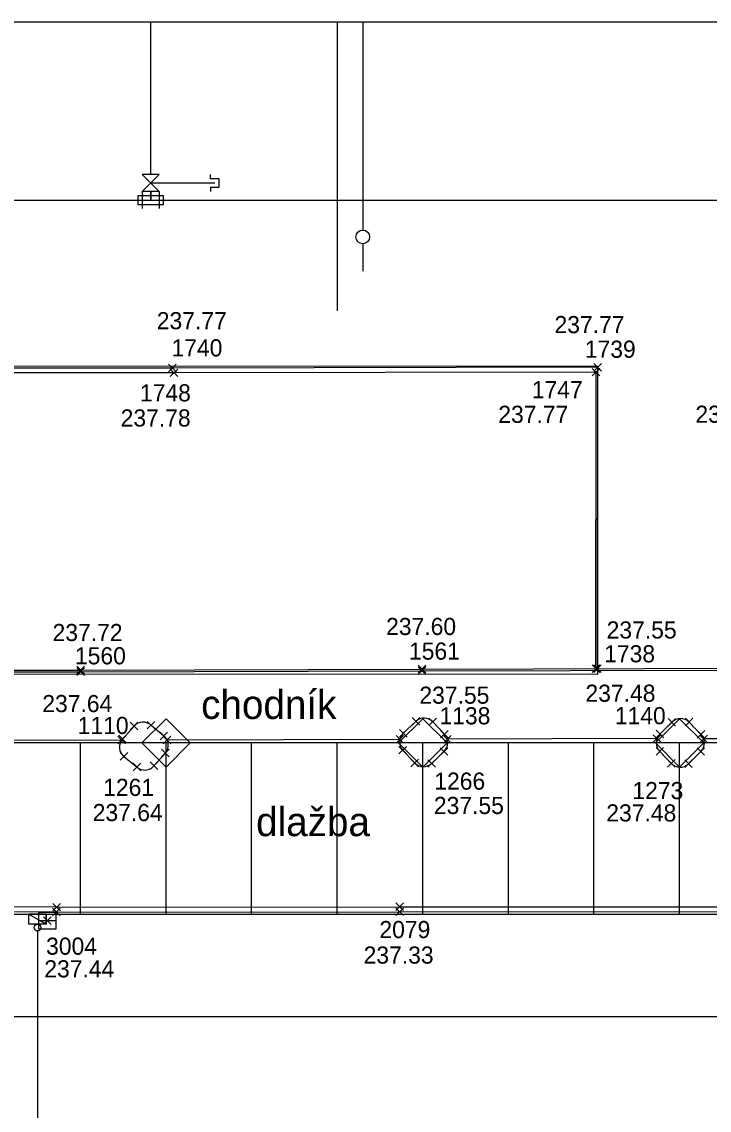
# Model space of a CAD drawing. Extents: x -264165 to -263733, y -1242319 to -1242245.
# Drawn here: x -263871.28 to -263851.2, y -1242276.71 to -1242244.94 of the extents above; entities that cross this region are included whole.
import ezdxf

# ---------------------------------------------------------------- set-up
doc = ezdxf.new("R2010")
doc.units = 0
for name, color, linetype in [('KFA_BOD_CISLO', 7, 'Continuous'), ('KFA_BOD_SYMBOL', 7, 'Continuous'), ('KFA_BOD_VYSKA', 7, 'Continuous'), ('KFA_SO_20-2_OBRUBNIKY_DOLNA_HRANA', 7, 'Continuous'), ('KFA_SO_20-2_OBRUBNIKY_HORNA_HRANA', 7, 'Continuous'), ('KFA_UV_BOD_CISLO', 7, 'Continuous'), ('KFA_UV_BOD_SYMBOL', 7, 'Continuous'), ('KFA_UV_BOD_VYSKA', 7, 'Continuous'), ('POPIS', 7, 'Continuous'), ('PROJEKT_OBRUBNIKY_KOMUNIKACIE', 7, 'Continuous'), ('PROJEKT_TDZ_VODOROVNE', 7, 'Continuous'), ('RAM_NA_TLAC_1-250', 7, 'Continuous'), ('SITUACIA_DSP_2D', 7, 'Continuous'), ('ULICNA_VPUST_POKLOP', 7, 'Continuous')]:
    doc.layers.add(name, color=color, linetype=linetype)

msp = doc.modelspace()

# ---------------------------------------------------------------- linework, layer by layer
at = {"layer": 'KFA_BOD_SYMBOL'}
for p, q in [((-263866.993, -1242255.153), (-263866.772, -1242254.931)), ((-263866.772, -1242255.153), (-263866.993, -1242254.931)), ((-263866.946, -1242255.292), (-263866.725, -1242255.072)), ((-263866.725, -1242255.292), (-263866.946, -1242255.072)), ((-263854.617, -1242255.272), (-263854.396, -1242255.052)), ((-263854.396, -1242255.272), (-263854.617, -1242255.052)), ((-263854.568, -1242255.13), (-263854.347, -1242254.91)), ((-263854.347, -1242255.13), (-263854.568, -1242254.91)), ((-263869.674, -1242263.968), (-263869.453, -1242263.747)), ((-263869.453, -1242263.968), (-263869.674, -1242263.747)), ((-263869.674, -1242264.018), (-263869.453, -1242263.796)), ((-263869.453, -1242264.018), (-263869.674, -1242263.796)), ((-263859.704, -1242263.938), (-263859.482, -1242263.717)), ((-263859.482, -1242263.938), (-263859.704, -1242263.717)), ((-263859.704, -1242263.988), (-263859.482, -1242263.766)), ((-263859.482, -1242263.988), (-263859.704, -1242263.766)), ((-263854.622, -1242263.926), (-263854.4, -1242263.704)), ((-263854.4, -1242263.926), (-263854.622, -1242263.704)), ((-263854.576, -1242263.926), (-263854.355, -1242263.704)), ((-263854.355, -1242263.926), (-263854.576, -1242263.704)), ((-263868.116, -1242265.603), (-263867.894, -1242265.383)), ((-263867.894, -1242265.603), (-263868.116, -1242265.383)), ((-263867.616, -1242265.576), (-263867.394, -1242265.355)), ((-263867.394, -1242265.576), (-263867.616, -1242265.355)), ((-263859.882, -1242265.467), (-263859.66, -1242265.245)), ((-263859.66, -1242265.467), (-263859.882, -1242265.245)), ((-263859.389, -1242265.48), (-263859.167, -1242265.258)), ((-263859.167, -1242265.48), (-263859.389, -1242265.258)), ((-263852.404, -1242265.492), (-263852.182, -1242265.271)), ((-263852.182, -1242265.492), (-263852.404, -1242265.271)), ((-263851.899, -1242265.487), (-263851.678, -1242265.265)), ((-263851.678, -1242265.487), (-263851.899, -1242265.265)), ((-263868.478, -1242266.014), (-263868.257, -1242265.792)), ((-263868.257, -1242266.014), (-263868.478, -1242265.792)), ((-263868.451, -1242265.981), (-263868.23, -1242265.761)), ((-263868.23, -1242265.981), (-263868.451, -1242265.761)), ((-263867.245, -1242265.891), (-263867.024, -1242265.671)), ((-263867.024, -1242265.891), (-263867.245, -1242265.671)), ((-263867.149, -1242266.012), (-263866.927, -1242265.791)), ((-263866.927, -1242266.012), (-263867.149, -1242265.791)), ((-263860.349, -1242265.991), (-263860.128, -1242265.769)), ((-263860.128, -1242265.991), (-263860.349, -1242265.769)), ((-263860.252, -1242265.812), (-263860.03, -1242265.592)), ((-263860.03, -1242265.812), (-263860.252, -1242265.592)), ((-263859.047, -1242265.84), (-263858.826, -1242265.62)), ((-263858.826, -1242265.84), (-263859.047, -1242265.62)), ((-263858.964, -1242265.988), (-263858.742, -1242265.766)), ((-263858.742, -1242265.988), (-263858.964, -1242265.766)), ((-263852.835, -1242265.965), (-263852.614, -1242265.745)), ((-263852.614, -1242265.965), (-263852.835, -1242265.745)), ((-263852.747, -1242265.833), (-263852.525, -1242265.612)), ((-263852.525, -1242265.833), (-263852.747, -1242265.612)), ((-263851.555, -1242265.846), (-263851.334, -1242265.624)), ((-263851.334, -1242265.846), (-263851.555, -1242265.624)), ((-263851.475, -1242265.978), (-263851.253, -1242265.758)), ((-263851.253, -1242265.978), (-263851.475, -1242265.758)), ((-263867.197, -1242266.393), (-263866.976, -1242266.171)), ((-263866.976, -1242266.393), (-263867.197, -1242266.171)), ((-263860.269, -1242266.306), (-263860.047, -1242266.085)), ((-263860.047, -1242266.306), (-263860.269, -1242266.085)), ((-263859.058, -1242266.345), (-263858.837, -1242266.123)), ((-263858.837, -1242266.345), (-263859.058, -1242266.123)), ((-263852.756, -1242266.343), (-263852.535, -1242266.122)), ((-263852.535, -1242266.343), (-263852.756, -1242266.122)), ((-263851.558, -1242266.343), (-263851.337, -1242266.123)), ((-263851.337, -1242266.343), (-263851.558, -1242266.123)), ((-263868.41, -1242266.488), (-263868.189, -1242266.266)), ((-263868.189, -1242266.488), (-263868.41, -1242266.266)), ((-263859.916, -1242266.678), (-263859.694, -1242266.458)), ((-263859.694, -1242266.678), (-263859.916, -1242266.458)), ((-263859.421, -1242266.694), (-263859.2, -1242266.474)), ((-263859.2, -1242266.694), (-263859.421, -1242266.474)), ((-263852.42, -1242266.693), (-263852.198, -1242266.471)), ((-263852.198, -1242266.693), (-263852.42, -1242266.471)), ((-263851.919, -1242266.704), (-263851.698, -1242266.482)), ((-263851.698, -1242266.704), (-263851.919, -1242266.482)), ((-263868.028, -1242266.802), (-263867.807, -1242266.58)), ((-263867.807, -1242266.802), (-263868.028, -1242266.58)), ((-263867.531, -1242266.759), (-263867.31, -1242266.539)), ((-263867.31, -1242266.759), (-263867.531, -1242266.539)), ((-263870.381, -1242271.034), (-263870.16, -1242270.812)), ((-263870.16, -1242271.034), (-263870.381, -1242270.812)), ((-263870.378, -1242270.889), (-263870.157, -1242270.667)), ((-263870.157, -1242270.889), (-263870.378, -1242270.667)), ((-263860.357, -1242271.025), (-263860.136, -1242270.803)), ((-263860.136, -1242271.025), (-263860.357, -1242270.803)), ((-263860.355, -1242270.877), (-263860.133, -1242270.656)), ((-263860.133, -1242270.877), (-263860.355, -1242270.656))]:
    msp.add_line(p, q, dxfattribs=at)
at = {"layer": 'KFA_SO_20-2_OBRUBNIKY_DOLNA_HRANA'}
for points in [[(-263870.27, -1242270.923), (-263879.971, -1242270.913), (-263889.978, -1242270.919), (-263899.995, -1242270.919), (-263908.997, -1242270.923), (-263917.4, -1242270.885)], [(-263870.268, -1242270.778), (-263879.968, -1242270.77), (-263889.973, -1242270.776), (-263899.989, -1242270.776), (-263908.993, -1242270.778), (-263917.158, -1242270.747)], [(-263870.27, -1242270.923), (-263860.247, -1242270.914), (-263850.285, -1242270.903), (-263840.274, -1242270.913), (-263830.254, -1242270.929), (-263819.233, -1242270.965)], [(-263870.268, -1242270.778), (-263860.244, -1242270.766), (-263850.281, -1242270.766), (-263840.271, -1242270.772), (-263830.256, -1242270.782), (-263819.239, -1242270.817)]]:
    msp.add_lwpolyline(points, dxfattribs=at)
at = {"layer": 'KFA_SO_20-2_OBRUBNIKY_HORNA_HRANA'}
for p, q in [((-263868.34, -1242265.871), (-263868.005, -1242265.493)), ((-263867.505, -1242265.465), (-263867.134, -1242265.781)), ((-263860.141, -1242265.702), (-263859.771, -1242265.356)), ((-263859.278, -1242265.369), (-263858.937, -1242265.73)), ((-263852.636, -1242265.722), (-263852.293, -1242265.381)), ((-263851.789, -1242265.376), (-263851.444, -1242265.735)), ((-263852.725, -1242265.855), (-263858.853, -1242265.877)), ((-263845.254, -1242265.858), (-263851.364, -1242265.868)), ((-263868.367, -1242265.903), (-263874.969, -1242265.925)), ((-263860.238, -1242265.88), (-263867.038, -1242265.901)), ((-263868.3, -1242266.377), (-263867.917, -1242266.691)), ((-263867.086, -1242266.282), (-263867.421, -1242266.649)), ((-263859.805, -1242266.568), (-263860.158, -1242266.195)), ((-263858.948, -1242266.234), (-263859.311, -1242266.584)), ((-263852.309, -1242266.582), (-263852.645, -1242266.232)), ((-263851.448, -1242266.233), (-263851.808, -1242266.593))]:
    msp.add_line(p, q, dxfattribs=at)
for points in [[(-263854.465, -1242263.815), (-263854.458, -1242255.02), (-263866.883, -1242255.042), (-263883.752, -1242255.044), (-263902.029, -1242255.047), (-263909.175, -1242255.048), (-263919.956, -1242255.04), (-263920.002, -1242255.04)], [(-263854.511, -1242263.815), (-263854.507, -1242255.162), (-263866.835, -1242255.182), (-263883.768, -1242255.184), (-263902.097, -1242255.191), (-263916.995, -1242263.915)], [(-263909.527, -1242263.897), (-263899.537, -1242263.895), (-263889.544, -1242263.882), (-263879.556, -1242263.864), (-263869.563, -1242263.857), (-263859.593, -1242263.827), (-263846.594, -1242263.797), (-263839.607, -1242263.784)], [(-263909.527, -1242263.947), (-263899.537, -1242263.945), (-263889.544, -1242263.932), (-263879.556, -1242263.914), (-263869.563, -1242263.907), (-263859.593, -1242263.877), (-263846.594, -1242263.847), (-263839.607, -1242263.834)]]:
    msp.add_lwpolyline(points, dxfattribs=at)
for centre, major_axis, ratio, start_param, end_param in [((-263867.741, -1242265.732), (-0.28, -0.22), 0.999509, 3.322445, 4.88112), ((-263859.531, -1242265.608), (-0.015, 0.348), 0.999793, 5.425764, 7.000161), ((-263852.039, -1242265.627), (-0.255, -0.245), 0.999795, 3.164307, 4.750014), ((-263868.092, -1242266.106), (0.027, -0.34), 0.99996, 3.874031, 5.550747), ((-263867.354, -1242266.055), (-0.17, 0.308), 0.999987, 3.505695, 5.102454), ((-263859.886, -1242265.958), (0.035, -0.359), 0.999882, 3.828047, 5.331937), ((-263859.199, -1242265.977), (0.277, 0.23), 0.999582, 4.791611, 6.343429), ((-263852.393, -1242265.981), (-0.023, -0.355), 0.99913, 3.960362, 5.558485), ((-263851.702, -1242265.982), (0.354, 0.05), 0.999652, 5.365324, 6.90704), ((-263867.69, -1242266.429), (0.337, -0.085), 0.998785, 4.246278, 5.84268), ((-263859.55, -1242266.332), (0.125, -0.324), 0.99994, 5.090538, 6.673957), ((-263852.053, -1242266.343), (0.35, -0.008), 0.999955, 3.915372, 5.509406)]:
    msp.add_ellipse(centre, major_axis=major_axis, ratio=ratio, start_param=start_param, end_param=end_param, dxfattribs=at)
at = {"layer": 'KFA_UV_BOD_SYMBOL'}
for p, q in [((-263870.648, -1242271.282), (-263870.427, -1242271.062)), ((-263870.427, -1242271.282), (-263870.648, -1242271.062))]:
    msp.add_line(p, q, dxfattribs=at)
at = {"layer": 'PROJEKT_OBRUBNIKY_KOMUNIKACIE'}
for p, q in [((-263807.068, -1242265.987), (-263917.08, -1242265.983)), ((-263917.578, -1242270.983), (-263807.068, -1242270.982))]:
    msp.add_line(p, q, dxfattribs=at)
for points in [[(-263854.468, -1242263.985), (-263917.08, -1242263.982), (-263901.868, -1242254.982), (-263854.468, -1242254.985), (-263854.468, -1242263.985)], [(-263867.068, -1242265.279), (-263866.361, -1242265.986), (-263867.068, -1242266.694), (-263867.775, -1242265.986), (-263867.068, -1242265.279)], [(-263859.568, -1242265.279), (-263858.861, -1242265.986), (-263859.568, -1242266.694), (-263860.275, -1242265.986), (-263859.568, -1242265.279)], [(-263852.068, -1242265.279), (-263851.361, -1242265.986), (-263852.068, -1242266.694), (-263852.775, -1242265.986), (-263852.068, -1242265.279)]]:
    msp.add_lwpolyline(points, dxfattribs=at)
at = {"layer": 'PROJEKT_TDZ_VODOROVNE'}
for p, q in [((-263869.568, -1242270.982), (-263869.568, -1242265.982)), ((-263867.068, -1242270.982), (-263867.068, -1242265.982)), ((-263864.568, -1242270.982), (-263864.568, -1242265.982)), ((-263862.068, -1242270.982), (-263862.068, -1242265.982)), ((-263859.568, -1242270.982), (-263859.568, -1242265.982)), ((-263857.068, -1242270.982), (-263857.068, -1242265.982)), ((-263854.568, -1242270.982), (-263854.568, -1242265.982)), ((-263852.068, -1242270.982), (-263852.068, -1242265.982)), ((-263817.068, -1242273.982), (-263917.477, -1242273.982))]:
    msp.add_line(p, q, dxfattribs=at)
at = {"layer": 'RAM_NA_TLAC_1-250'}
msp.add_lwpolyline([(-264165.363, -1242244.935), (-263732.863, -1242244.935), (-263732.863, -1242319.185), (-264165.363, -1242319.185)], close=True, dxfattribs=at)
at = {"layer": 'SITUACIA_DSP_2D'}
for p, q in [((-263867.518, -1242249.39), (-263867.518, -1242244.935)), ((-263862.068, -1242244.935), (-263862.068, -1242253.368)), ((-263861.32, -1242244.935), (-263861.321, -1242251.015)), ((-263867.268, -1242249.39), (-263867.768, -1242249.39)), ((-263867.768, -1242249.89), (-263867.268, -1242249.39)), ((-263867.768, -1242249.39), (-263867.268, -1242249.89)), ((-263867.518, -1242249.64), (-263865.643, -1242249.64)), ((-263865.768, -1242249.515), (-263865.768, -1242249.39)), ((-263865.518, -1242249.515), (-263865.768, -1242249.515)), ((-263865.518, -1242249.765), (-263865.518, -1242249.515)), ((-263867.268, -1242249.89), (-263867.768, -1242249.89)), ((-263867.768, -1242249.89), (-263867.768, -1242250.39)), ((-263867.518, -1242250.14), (-263867.518, -1242249.89)), ((-263867.518, -1242249.89), (-263867.518, -1242250.14)), ((-263867.268, -1242249.89), (-263867.268, -1242250.39)), ((-263865.768, -1242249.765), (-263865.768, -1242249.89)), ((-263865.768, -1242249.765), (-263865.518, -1242249.765)), ((-263924.143, -1242250.14), (-263788.143, -1242250.14)), ((-263867.143, -1242250.015), (-263867.893, -1242250.015)), ((-263867.893, -1242250.015), (-263867.893, -1242250.265)), ((-263867.893, -1242250.265), (-263867.143, -1242250.265)), ((-263867.143, -1242250.265), (-263867.143, -1242250.015)), ((-263861.321, -1242251.415), (-263861.321, -1242252.215)), ((-263871.074, -1242270.983), (-263870.574, -1242270.983)), ((-263871.074, -1242271.273), (-263871.074, -1242270.983)), ((-263871.074, -1242270.983), (-263870.574, -1242271.273)), ((-263871.074, -1242270.983), (-263870.574, -1242271.273)), ((-263870.574, -1242270.983), (-263871.074, -1242270.983)), ((-263870.574, -1242271.273), (-263871.074, -1242271.273)), ((-263870.574, -1242270.983), (-263870.574, -1242271.273)), ((-263870.574, -1242271.273), (-263870.574, -1242270.983)), ((-263870.824, -1242271.473), (-263870.824, -1242283.482))]:
    msp.add_line(p, q, dxfattribs=at)
msp.add_lwpolyline([(-263854.468, -1242263.985), (-263917.08, -1242263.982), (-263901.868, -1242254.982), (-263854.468, -1242254.985), (-263854.468, -1242263.985)], dxfattribs=at)
for points in [[(-263867.068, -1242265.279), (-263866.361, -1242265.986), (-263867.068, -1242266.693), (-263867.775, -1242265.986)], [(-263859.568, -1242265.279), (-263858.861, -1242265.986), (-263859.568, -1242266.693), (-263860.275, -1242265.986)], [(-263852.068, -1242265.279), (-263851.361, -1242265.986), (-263852.068, -1242266.693), (-263852.775, -1242265.986)]]:
    msp.add_lwpolyline(points, close=True, dxfattribs=at)
for centre, radius in [((-263861.321, -1242251.215), 0.2), ((-263870.824, -1242271.373), 0.1)]:
    msp.add_circle(centre, radius, dxfattribs=at)
at = {"layer": 'ULICNA_VPUST_POKLOP'}
msp.add_line((-263870.537, -1242271.172), (-263870.537, -1242271.172), dxfattribs=at)
msp.add_lwpolyline([(-263870.787, -1242271.172), (-263870.787, -1242270.922), (-263870.287, -1242270.922), (-263870.287, -1242271.422), (-263870.787, -1242271.422), (-263870.787, -1242271.172), (-263870.287, -1242271.172)], dxfattribs=at)

# ---------------------------------------------------------------- texts
at = {"layer": 'KFA_BOD_CISLO'}
for s, p in [('1740', (-263866.91, -1242254.703)), ('1739', (-263854.836, -1242254.742)), ('1748', (-263867.831, -1242256.016)), ('1747', (-263856.384, -1242255.922)), ('1560', (-263869.73, -1242263.691)), ('1561', (-263859.972, -1242263.554)), ('1738', (-263854.271, -1242263.632)), ('1110', (-263869.65, -1242265.725)), ('1138', (-263859.082, -1242265.442)), ('1140', (-263853.96, -1242265.44)), ('1261', (-263868.906, -1242267.532)), ('1266', (-263859.233, -1242267.349)), ('1273', (-263853.446, -1242267.626)), ('2079', (-263860.836, -1242271.681))]:
    msp.add_text(s, height=0.5, dxfattribs=at).set_placement(p)
at = {"layer": 'KFA_BOD_VYSKA'}
for s, p in [('237.77', (-263867.34, -1242253.91)), ('237.77', (-263855.721, -1242254.024)), ('237.78', (-263868.395, -1242256.749)), ('237.77', (-263857.363, -1242256.642)), ('237.76', (-263851.604, -1242256.64)), ('237.60', (-263860.641, -1242262.835)), ('237.72', (-263870.384, -1242263.011)), ('237.55', (-263854.199, -1242262.937)), ('237.48', (-263854.817, -1242264.784)), ('237.64', (-263870.684, -1242265.086)), ('237.55', (-263859.668, -1242264.841)), ('237.64', (-263869.212, -1242268.266)), ('237.55', (-263859.245, -1242268.06)), ('237.48', (-263854.209, -1242268.277)), ('237.33', (-263861.298, -1242272.426))]:
    msp.add_text(s, height=0.5, dxfattribs=at).set_placement(p)
at = {"layer": 'KFA_UV_BOD_CISLO'}
msp.add_text('3004', height=0.5, dxfattribs=at).set_placement((-263870.573, -1242272.167))
at = {"layer": 'KFA_UV_BOD_VYSKA'}
msp.add_text('237.44', height=0.5, dxfattribs=at).set_placement((-263870.625, -1242272.828))
at = {"layer": 'POPIS'}
for s, p in [('chodník', (-263866.043, -1242265.285)), ('dlažba', (-263864.438, -1242268.705))]:
    msp.add_text(s, height=0.8438, dxfattribs=at).set_placement(p)

doc.saveas('drawing.dxf')
